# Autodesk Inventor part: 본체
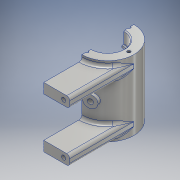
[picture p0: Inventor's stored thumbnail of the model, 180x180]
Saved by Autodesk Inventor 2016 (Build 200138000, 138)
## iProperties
Created: 2020-07
Part Number: 본체
Material: 알루미늄 6061
Document SubType Name: Modeling
Designer: pc-04
Density: 2.7 g/cm^3
Appearance: 알루미늄 - 평지
Author: pc-04
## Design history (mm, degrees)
sketch "스케치1"
  geometry: C1 r 26 at (0, 0); 1 further point
  constraints: 1 centre point, 1 coincident
  dimensions: "d0" = 52 diameter of C1
extrude "돌출1" new body sketch "스케치1" stored distance "d1" = 70; taper "d2" = 0 deg
sketch "스케치2"
  geometry: L1 (26, 0)-(26, -64); L2 (26, -64)-(-26, -64); L3 (-26, -64)-(-26, 0); L4 (-26, 0)-(26, 0); A1 r 26 centre (0, 0) between (26, 0) and (-26, 0) reference; 1 further point
  constraints: 8 end point, 2 point on circle, 1 perpendicular, 1 tangent, 1 vertical
  dimensions: "d3" = 64 distance of L1.start L1.end; "d4" = 52 distance of L1.end L2.end; "d5" = 64 distance of L2.end L3.end; "d6" = 52 distance of L3.end L1.start (derived)
extrude "돌출2" join sketch "스케치2" stored distance "d7" = 60; taper "d8" = 0 deg
sketch "스케치3"
  geometry: L1 (60, 0)-(0, 0) reference; L2 (30, 0)-(10, 0); L3 (10, 0)-(10, 64); L4 (10, 64)-(50, 64); L5 (50, 64)-(50, 0); L6 (50, 0)-(30, 0); 1 further point
  constraints: 10 end point, 2 perpendicular, 2 point on line, 1 midpoint
  dimensions: "d9" = 20 distance of L2.start L2.end; "d10" = 64 distance of L2.end L3.end; "d11" = 40 distance of L3.end L4.end; "d12" = 64 distance of L4.end L5.end
extrude "돌출3" cut sketch "스케치3" distance "d13" = 60; taper "d14" = 0 deg
sketch "스케치4"
  geometry: C1 r 26 at (0, 0); 1 further point
  constraints: 1 centre point, 1 coincident
  dimensions: "d15" = 52 diameter of C1
extrude "돌출4" join sketch "스케치4" stored distance "d16" = 70; taper "d17" = 0 deg
sketch "스케치5"
  geometry: L1 (26, 35)-(-26, 35) reference; L2 (0, 35)-(16, 35); L3 (16, 35)-(16, 23); L4 (16, 23)-(14, 23); L5 (0, 0)-(21, 0); L6 (21, 0)-(21, 21); L7 (21, 21)-(14, 21); L8 (14, 21)-(14, 23); L9 (21, 0)-(21, -21); L10 (21, -21)-(14, -21); L11 (14, -21)-(14, -23); L12 (-26, -35)-(26, -35) reference; L13 (0, -35)-(16, -35); L14 (16, -35)-(16, -23); L15 (16, -23)-(14, -23); L16 (0, 35)-(0, -35)
  constraints: 28 end point, 7 perpendicular, 2 midpoint, 2 point on line, 2 vertical, 1 horizontal
  dimensions: "d18" = 16 distance of L2.start L2.end; "d19" = 12 distance of L2.end L3.end; "d20" = 2 distance of L3.end L4.end; "d21" = 21 distance of L5.start L5.end; "d22" = 21 distance of L5.end L6.end; "d23" = 7 distance of L6.end L7.end; "d24" = 2 distance of L7.end L4.end (derived); "d25" = 21 distance of L5.end L9.end; "d26" = 7 distance of L9.end L10.end; "d27" = 2 distance of L10.end L11.end; "d28" = 16 distance of L13.start L13.end; "d29" = 12 distance of L13.end L14.end
revolve "회전1" sketch "스케치5" stored, may be unused: angle "d30" = 90 deg
chamfer "모따기1" distance "d31" = 1; stored, may be unused: second distance "d32" = 2, angle "d33" = 45 deg; dims "d18" = 16
fillet "모깎기1" dims "d37" = 3
sketch "스케치6"
  geometry: L1 (0, 0)-(9.919, -27.251); L2 (0, 0)-(0, -64); L3 (26, -64)-(-26, -64) reference; L4 (9.919, -27.251)-(15.557, -25.199); L5 (15.557, -25.199)-(12.992, -18.151); L6 (12.992, -18.151)-(7.353, -20.203)
  constraints: 10 end point, 2 perpendicular, 1 midpoint, 1 point on line
  dimensions: "d38" = 29 distance of L1.start L1.end; "d39" = 20 deg angle of L1 L2; "d40" = 6 distance of L1.end L4.end; "d41" = 7.5 distance of L4.end L5.end
revolve "회전2" sketch "스케치6" stored, may be unused: angle "d42" = 90 deg
sketch "스케치7"
  geometry: 2 further points
  constraints: 1 coincident
hole "구멍1" sketch "스케치7" at (0, 0) diameter "d43" = 4.917; stored, may be unused: countersink angle "d47" = 90 deg, drill point angle "d49" = 118 deg; dims "d44" = 15, "d45" = 4, "d46" = 2, "d48" = 15
sketch "스케치8"
  geometry: A1 r 21 centre (0, 0) between (0, 21) and (-21, 0); 3 further points
  constraints: 4 point on circle, 1 centre point, 1 coincident
  dimensions: "d50" = 42 diameter of A1
hole "구멍2" sketch "스케치8" at (0, 21), (-21, 0), (0, -21), (21, 0) diameter "d51" = 3.242; stored, may be unused: countersink angle "d55" = 90 deg, drill point angle "d57" = 118 deg; dims "d52" = 8, "d53" = 4, "d54" = 2, "d56" = 10
sketch "스케치9"
  geometry: L1 (52, 0)-(0, 0) reference; L2 (26, 0)-(26, -9.948); L3 (26, -4.974)-(6, -4.974); L4 (26, -4.974)-(46, -4.974); L5 (0, -50)-(52, -50) reference; L6 (0, -60)-(52, -60) reference; L7 (26, -50)-(26, -60); L8 (26, -55)-(46, -55); L9 (26, -55)-(6, -55); 5 further points
  constraints: 12 end point, 5 midpoint, 4 coincident, 4 horizontal, 1 vertical
  dimensions: "d58" = 20 distance of L3.start L3.end; "d59" = 20 distance of L3.start L4.end; "d60" = 20 distance of L8.start L8.end; "d61" = 20 distance of L8.start L9.end
hole "구멍3" sketch "스케치9" at (46, -4.974), (6, -4.974), (6, -55), (46, -55) diameter "d62" = 4.134; stored, may be unused: countersink angle "d66" = 90 deg, drill point angle "d68" = 118 deg; dims "d63" = 8, "d64" = 4, "d65" = 2, "d67" = 10
sketch "스케치10"
  geometry: L1 (0, 26)-(0, 29); L2 (0, 29)-(-5, 29); L3 (-5, 29)-(-5, 22); L4 (-5, 22)-(0, 22); L5 (0, 22)-(0, 26); 2 further points
  constraints: 10 end point, 2 perpendicular, 1 point on line, 1 vertical, 1 vertical alignment, 1 other
  dimensions: "d69" = 3 distance of L1.start L1.end; "d70" = 5 distance of L1.end L2.end; "d71" = 7 distance of L2.end L3.end; "d72" = 5 distance of L3.end L4.end
revolve "회전3" sketch "스케치10" stored, may be unused: angle "d73" = 90 deg
sketch "스케치11"
  geometry: 2 further points
  constraints: 1 coincident
hole "구멍4" sketch "스케치11" at (0, 0) diameter "d74" = 4.917; stored, may be unused: countersink angle "d78" = 90 deg, drill point angle "d80" = 118 deg; dims "d75" = 12, "d76" = 4, "d77" = 2, "d79" = 17.1
fillet "모깎기2" dims "d81" = 3
node "작업 평면2"
sketch "스케치12"
  geometry: L1 (-2.577, -16.46)-(-2.577, 16.723); L2 (-2.577, 16.723)-(2.226, 16.723); L3 (2.226, 16.723)-(2.226, -16.46); L4 (2.226, -16.46)-(-2.577, -16.46); 1 further point
  constraints: 2 other
extrude "돌출5" join sketch "스케치12" stored distance "d82" = 1; taper "d83" = 0 deg
fillet "모깎기3" dims "d84" = 0.3
node "솔리드1"
mirror "대칭1"
